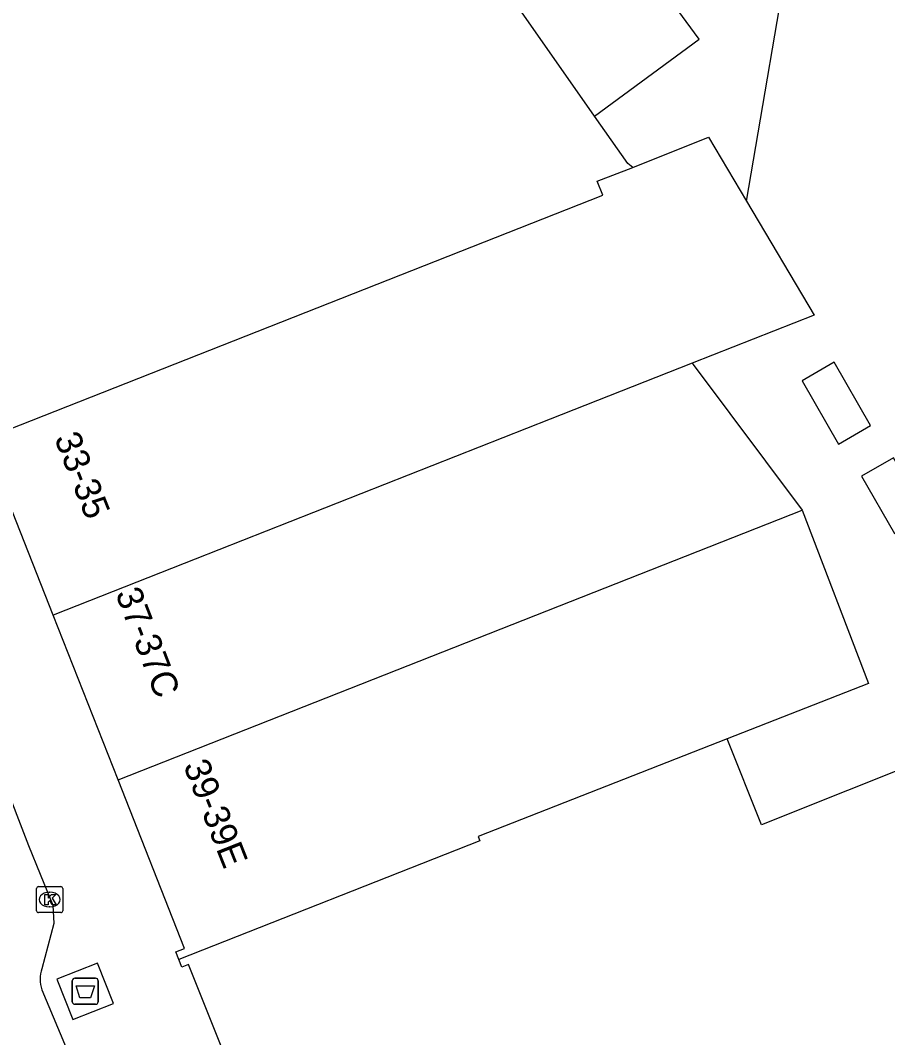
# Model space of a CAD drawing. Extents: x 161087 to 161922, y 382574 to 383873.
# Drawn here: x 161788.96 to 161822.2, y 382622.42 to 382661.41 of the extents above; entities that cross this region are included whole.
import ezdxf

# ---------------------------------------------------------------- set-up
doc = ezdxf.new("R2010")
doc.units = 0
for name, color, linetype in [('IMGEO_Afval_apart_plaats', 7, 'Continuous'), ('IMGEO_Kolk', 7, 'Continuous'), ('IMGEO_Pand', 7, 'Continuous'), ('IMGEO_Pand_nummerreeks', 7, 'Continuous'), ('IMGEO_Rijbaan_lokaal_open', 7, 'Continuous'), ('IMGEO_Voetpad_gesloten', 7, 'Continuous')]:
    doc.layers.add(name, color=color, linetype=linetype)

msp = doc.modelspace()

# ---------------------------------------------------------------- linework, layer by layer
at = {"layer": 'IMGEO_Afval_apart_plaats'}
for p, q in [((161790.952, 382623.8), (161790.952, 382624.6)), ((161790.952, 382624.6), (161790.952, 382623.8)), ((161791.052, 382624.7), (161791.842, 382624.7)), ((161791.842, 382624.7), (161791.052, 382624.7)), ((161791.942, 382624.6), (161791.942, 382623.8)), ((161791.942, 382623.8), (161791.942, 382624.6)), ((161791.842, 382623.7), (161791.052, 382623.7)), ((161791.052, 382623.7), (161791.842, 382623.7))]:
    msp.add_line(p, q, dxfattribs=at)
msp.add_lwpolyline([(161791.095, 382624.414), (161791.799, 382624.414), (161791.65, 382623.944), (161791.244, 382623.944), (161791.095, 382624.414)], dxfattribs=at)
for centre, start, end in [((161791.052, 382624.6), 90, 180), ((161791.052, 382624.6), 90, 180), ((161791.842, 382624.6), 0, 90), ((161791.842, 382624.6), 360, 90), ((161791.052, 382623.8), 180, 270), ((161791.052, 382623.8), 180, 270), ((161791.842, 382623.8), 270, 0), ((161791.842, 382623.8), 270, 0)]:
    msp.add_arc(centre, 0.1, start, end, dxfattribs=at)
at = {"layer": 'IMGEO_Kolk'}
for p, q in [((161789.584, 382627.287), (161789.584, 382628.139)), ((161789.659, 382628.213), (161790.511, 382628.213)), ((161790.072, 382627.993), (161790.097, 382627.993)), ((161790.585, 382628.139), (161790.585, 382627.287)), ((161790.511, 382627.213), (161789.659, 382627.213)), ((161790.095, 382627.433), (161790.07, 382627.433))]:
    msp.add_line(p, q, dxfattribs=at)
for points in [[(161789.584, 382627.287), (161789.584, 382628.139)], [(161789.659, 382628.213), (161790.511, 382628.213)], [(161790.585, 382628.139), (161790.585, 382627.287)], [(161789.905, 382627.913), (161790.028, 382627.913), (161790.028, 382627.762), (161790.158, 382627.913), (161790.322, 382627.913), (161790.176, 382627.762), (161790.329, 382627.513), (161790.177, 382627.513), (161790.092, 382627.677), (161790.028, 382627.61), (161790.028, 382627.513), (161789.905, 382627.513), (161789.905, 382627.913)], [(161790.511, 382627.213), (161789.659, 382627.213)]]:
    msp.add_lwpolyline(points, dxfattribs=at)
for centre, start, end in [((161789.661, 382628.137), 91.552, 178.448), ((161789.661, 382628.137), 91.552, 178.448), ((161790.509, 382628.137), 1.552, 88.448), ((161790.509, 382628.137), 1.552, 88.448), ((161789.661, 382627.289), 181.552, 268.448), ((161789.661, 382627.289), 181.552, 268.448), ((161790.509, 382627.289), 271.552, 358.448), ((161790.509, 382627.289), 271.552, 358.448)]:
    msp.add_arc(centre, 0.0765, start, end, dxfattribs=at)
for centre, major_axis, ratio, start_param, end_param in [((161790.071, 382627.713), (-0.387, 0.002), 0.722429, 4.712389, 7.853982), ((161790.096, 382627.713), (-0.39, 0.002), 0.717154, 1.570796, 4.712389)]:
    msp.add_ellipse(centre, major_axis=major_axis, ratio=ratio, start_param=start_param, end_param=end_param, dxfattribs=at)
at = {"layer": 'IMGEO_Pand'}
for points in [[(161816.781, 382654.482), (161818.589, 382665.042), (161822.196, 382667.68), (161813.932, 382678.982), (161825.17, 382687.2), (161824.016, 382688.779), (161825.218, 382694.071)], [(161810.963, 382657.741), (161814.973, 382660.691), (161802.286, 382677.941), (161801.952, 382678.394), (161799.757, 382677.491), (161799.979, 382676.953), (161800.307, 382676.156), (161787.995, 382671.093), (161778.798, 382667.31)], [(161810.963, 382657.741), (161801.407, 382671.4), (161797.252, 382669.737), (161792.609, 382667.879), (161793.107, 382666.634), (161790.297, 382665.51), (161781.07, 382661.815)], [(161812.431, 382655.769), (161812.234, 382655.924), (161810.963, 382657.741)], [(161812.431, 382655.769), (161815.327, 382656.927), (161816.781, 382654.482)], [(161787.559, 382645.353), (161811.28, 382654.704), (161811.068, 382655.241), (161812.431, 382655.769)], [(161816.781, 382654.482), (161819.381, 382650.11), (161814.709, 382648.268)], [(161814.709, 382648.268), (161790.217, 382638.612)], [(161814.709, 382648.268), (161814.748, 382648.215), (161818.92, 382642.636)], [(161818.917, 382647.597), (161820.309, 382645.17), (161821.541, 382645.877), (161820.148, 382648.304), (161818.917, 382647.597)], [(161790.217, 382638.612), (161787.709, 382644.974)], [(161823.686, 382642.442), (161822.422, 382644.645), (161821.195, 382643.941), (161822.459, 382641.738), (161823.686, 382642.442)], [(161792.705, 382632.301), (161818.92, 382642.636)], [(161818.92, 382642.636), (161821.456, 382635.995), (161816.041, 382633.872)], [(161792.705, 382632.301), (161790.217, 382638.612)], [(161816.041, 382633.872), (161806.499, 382630.132), (161806.567, 382629.961), (161795.036, 382625.415)], [(161836.385, 382629.733), (161831.536, 382630.953), (161824.122, 382632.789), (161823.951, 382633.215), (161817.36, 382630.577), (161816.041, 382633.872)], [(161795.036, 382625.415), (161794.918, 382625.711), (161795.25, 382625.844), (161792.705, 382632.301)], [(161802.325, 382607.929), (161795.404, 382625.221), (161795.154, 382625.121), (161795.036, 382625.415)]]:
    msp.add_lwpolyline(points, dxfattribs=at)
at = {"layer": 'IMGEO_Rijbaan_lokaal_open'}
for points in [[(161787.244, 382635.106), (161788.28, 382632.38), (161789.273, 382629.791), (161789.724, 382628.692), (161790.211, 382627.501), (161790.242, 382626.794), (161789.785, 382625.062)], [(161789.789, 382624.258), (161791.09, 382621.145), (161791.439, 382620.256)]]:
    msp.add_lwpolyline(points, dxfattribs=at)
msp.add_arc((161790.906, 382624.666), 1.189, 160.5298, 200.0403, dxfattribs=at)
at = {"layer": 'IMGEO_Voetpad_gesloten'}
msp.add_lwpolyline([(161792.529, 382623.735), (161791.919, 382625.279), (161790.364, 382624.665), (161790.974, 382623.121), (161792.529, 382623.735)], dxfattribs=at)

# ---------------------------------------------------------------- texts
at = {"layer": 'IMGEO_Pand_nummerreeks'}
for s, rotation, p in [('33-35', 291.5144, (161790.251, 382645.396)), ('37-37C', 291.1878, (161792.592, 382639.447)), ('39-39E', 291.5144, (161795.196, 382632.852))]:
    msp.add_text(s, height=1, rotation=rotation, dxfattribs=at).set_placement(p)

doc.saveas('drawing.dxf')
